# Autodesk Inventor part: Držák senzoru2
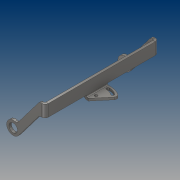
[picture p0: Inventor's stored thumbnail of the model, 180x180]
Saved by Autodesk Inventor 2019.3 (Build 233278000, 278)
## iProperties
Created: 2019-04
Part Number: Držák senzoru2
Material: Ocel, legovaná
Document SubType Name: Plech
Designer: B-hon
Density: 7.73 g/cm^3
Sheet Metal Rule: Výchozí_mm
Appearance: Pololeštěná
Author: B-hon
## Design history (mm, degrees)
node "Plocha1"
  sketch "Náčrt1"
    geometry: L1 (0, 0)-(-5, 0); L2 (0, 0)-(0, -25); L3 (0, -25)-(-5, -25); L4 (-5, -25)-(-48.835, -82.946); L5 (-5, 0)-(-52.442, -62.715); C1 r 9 at (-60, -74.5); A1 r 14 centre (-60, -74.5) between (-52.442, -62.715) and (-48.835, -82.946)
    constraints: 10 end point, 2 centre point, 2 point on circle, 1 horizontal, 1 perpendicular, 1 tangent, 1 vertical
    dimensions: "d0" = 5 distance of L1.start L1.end; "d1" = 25 distance of L1.start L2.end; "d2" = 5 distance of L2.end L3.end; "d3" = 18 diameter of C1; "d4" = 5 radial gap between concentric circles of C1 A1; "d5" = 74.5 distance from line of C1.centre L1; "d6" = 60 distance from line of L2 C1.centre; "d18" = 0 deg angle of L4 L5
node "Obruba1"
mirror "Zrcadlit1"
sketch "Náčrt3"
  geometry: L1 (0, -226)-(0, 0) reference; L2 (5, 0)-(5, -226) reference; L3 (0, -80)-(5, -80); L4 (5, -80)-(5, -125); L5 (5, -125)-(0, -125); L6 (0, -125)-(0, -80); L7 (-7, 7)-(-50.835, 7) reference; 1 further point
  constraints: 8 end point, 2 parallel, 2 point on line, 1 horizontal, 1 perpendicular
  dimensions: "d19" = 45 distance of L3.end L4.end; "d20" = 87 distance between parallel lines of L3 L7
extrude "Vysunutí1" join sketch "Náčrt3" distance "d21" = 1; taper "d22" = 0 deg
node "Obruba2"
sketch "Náčrt5"
  geometry: L1 (-53, 45)-(-53, 0) reference; L2 (0, 0)-(-53, 0) reference; L3 (-50, 0)-(-21.075, 34.472); L4 (-50, 0)-(-0.255, 0); L5 (-50, 0)-(-47.166, -8.083); L6 (-47.166, -8.083)-(11.557, -4.565); L7 (11.557, -4.565)-(9.31, 49.956); L8 (9.31, 49.956)-(-51.954, 53.474); L9 (0, 45)-(-53, 45) reference; L10 (-50, 45)-(-51.954, 53.474); A1 r 45 centre (-50, 0) between (-21.075, 34.472) and (-50, 45); 1 further point
  constraints: 14 end point, 2 point on circle, 2 point on line, 1 centre point, 1 coincident, 1 horizontal
  dimensions: "d36" = 50 deg angle of L4 L3; "d37" = 3 distance of L10.start L1.start; "d38" = 3 distance of L3.start L1.end
extrude "Vysunutí2" cut sketch "Náčrt5" extent not by distance; stored distance "d39" = 1; taper "d40" = 0 deg
sketch "Náčrt7"
  geometry: L1 (3, 0)-(31.925, 34.472) reference; L2 (0, 45)-(0, 0) reference; C1 r 3 at (6, 12.91); 1 further point
  constraints: 1 centre point
  dimensions: "d47" = 6 diameter of C1; "d48" = 6 distance from line of L1 C1.centre; "d49" = 6 distance from line of L2 C1.centre
extrude "Vysunutí4" cut sketch "Náčrt7" extent not by distance; stored distance "d50" = 1; taper "d51" = 0 deg
sketch "Náčrt8"
  geometry: C1 r 3 at (6, 12.91) reference; A1 r 25 centre (6, 12.91) between (21.392, 32.61) and (6, 37.91); A2 r 28 centre (6, 12.91) between (23.239, 34.974) and (6, 40.91); A3 r 22 centre (6, 12.91) between (19.545, 30.246) and (6, 34.91); A4 r 3 centre (21.392, 32.61) between (19.545, 30.246) and (23.239, 34.974); A5 r 3 centre (6, 37.91) between (6, 40.91) and (6, 34.91); 1 further point
  constraints: 10 point on circle, 5 centre point, 4 tangent, 1 coincident, 1 vertical alignment
  dimensions: "d52" = 6 diameter of A4; "d53" = 25 radius of A1; "d54" = 38 deg dimension on A1.centre A1.start A1.end
extrude "Vysunutí5" cut sketch "Náčrt8" extent not by distance; stored distance "d55" = 1; taper "d56" = 0 deg
sketch "Náčrt9"
  geometry: 1 further point
fillet "Zaoblení1" dims "d57" = 6
fillet "Zaoblení2" dims "d58" = 6
node "Těleso1"
feature "Deska1" dims "d7" = 5 (= Tloušťka)
sketch "Náčrt2"
  geometry: L1 through (12.5, 0) direction (-1, 0); L2 through (0, -56.5) direction (0, -1); L3 (0, -113)-(25, -113); L4 (25, -113)-(25, 0)
  constraints: 6 end point, 1 horizontal, 1 perpendicular, 1 vertical
feature "Deska2" dims "d7" = 5 (= Tloušťka), "d8" = 5 (= ŠířkaVýštipu), "d9" = 2.5 (= HloubkaVýštipu), "d10" = 10 (= MinimálníZbytek), "d11" = 5 (= PřechodovýPoloměr), "d12" = 120, "d13" = 90 deg, "d14" = 2, "d15" = 20 (= VelikostRohovéhoVýštipu), "d16" = 5 (= VelikostMezery), "d17" = 5 (= VelikostJacobihoPoloměru), "MezeraVystřižení" = 0.01
feature "Ohyb1" dims "d7" = 5 (= Tloušťka), "d8" = 5 (= ŠířkaVýštipu), "d9" = 2.5 (= HloubkaVýštipu), "d10" = 10 (= MinimálníZbytek), "d11" = 5 (= PřechodovýPoloměr), "d12" = 120, "d13" = 90 deg, "d14" = 2, "MezeraVystřižení" = 0.01
feature "Roh1" dims "d12" = 120, "d13" = 90 deg, "d15" = 20 (= VelikostRohovéhoVýštipu), "d16" = 5 (= VelikostMezery), "d17" = 5 (= VelikostJacobihoPoloměru)
sketch "Náčrt4"
  geometry: L1 through (0, 22.5) direction (2.71e-16, -1); L2 through (26.5, 0) direction (1, 3.35e-16); L3 (53, 0)-(53, 45); L4 (53, 45)-(0, 45)
  constraints: 6 end point, 1 horizontal, 1 perpendicular, 1 vertical
feature "Deska3" dims "d7" = 5 (= Tloušťka), "d23" = 5 (= ŠířkaVýštipu), "d24" = 2.5 (= HloubkaVýštipu), "d25" = 10 (= MinimálníZbytek), "d26" = 5 (= PřechodovýPoloměr), "d27" = 60, "d28" = 90 deg, "d29" = 2, "d30" = 20 (= VelikostRohovéhoVýštipu), "d31" = 5 (= VelikostMezery), "d32" = 5 (= VelikostJacobihoPoloměru), "MezeraVystřižení" = 0.01
feature "Ohyb2" dims "d7" = 5 (= Tloušťka), "d23" = 5 (= ŠířkaVýštipu), "d24" = 2.5 (= HloubkaVýštipu), "d25" = 10 (= MinimálníZbytek), "d26" = 5 (= PřechodovýPoloměr), "d27" = 60, "d28" = 90 deg, "d29" = 2, "MezeraVystřižení" = 0.01
feature "Roh2" dims "d27" = 60, "d28" = 90 deg, "d30" = 20 (= VelikostRohovéhoVýštipu), "d31" = 5 (= VelikostMezery), "d32" = 5 (= VelikostJacobihoPoloměru)
other parameters: "Tloušťka" = 5 (derived), "KSoučinitel" = 4.4, "PoloměrOhybu" = 5 (= Tloušťka), "ŠířkaVýštipu" = 5 (= Tloušťka), "HloubkaVýštipu" = 2.5 (= 0.5 x Tloušťka), "PřechodovýPoloměr" = 5 (= PoloměrOhybu), "VelikostJacobihoPoloměru" = 5 (= PoloměrOhybu), "VelikostMezery" = 5 (= Tloušťka)
